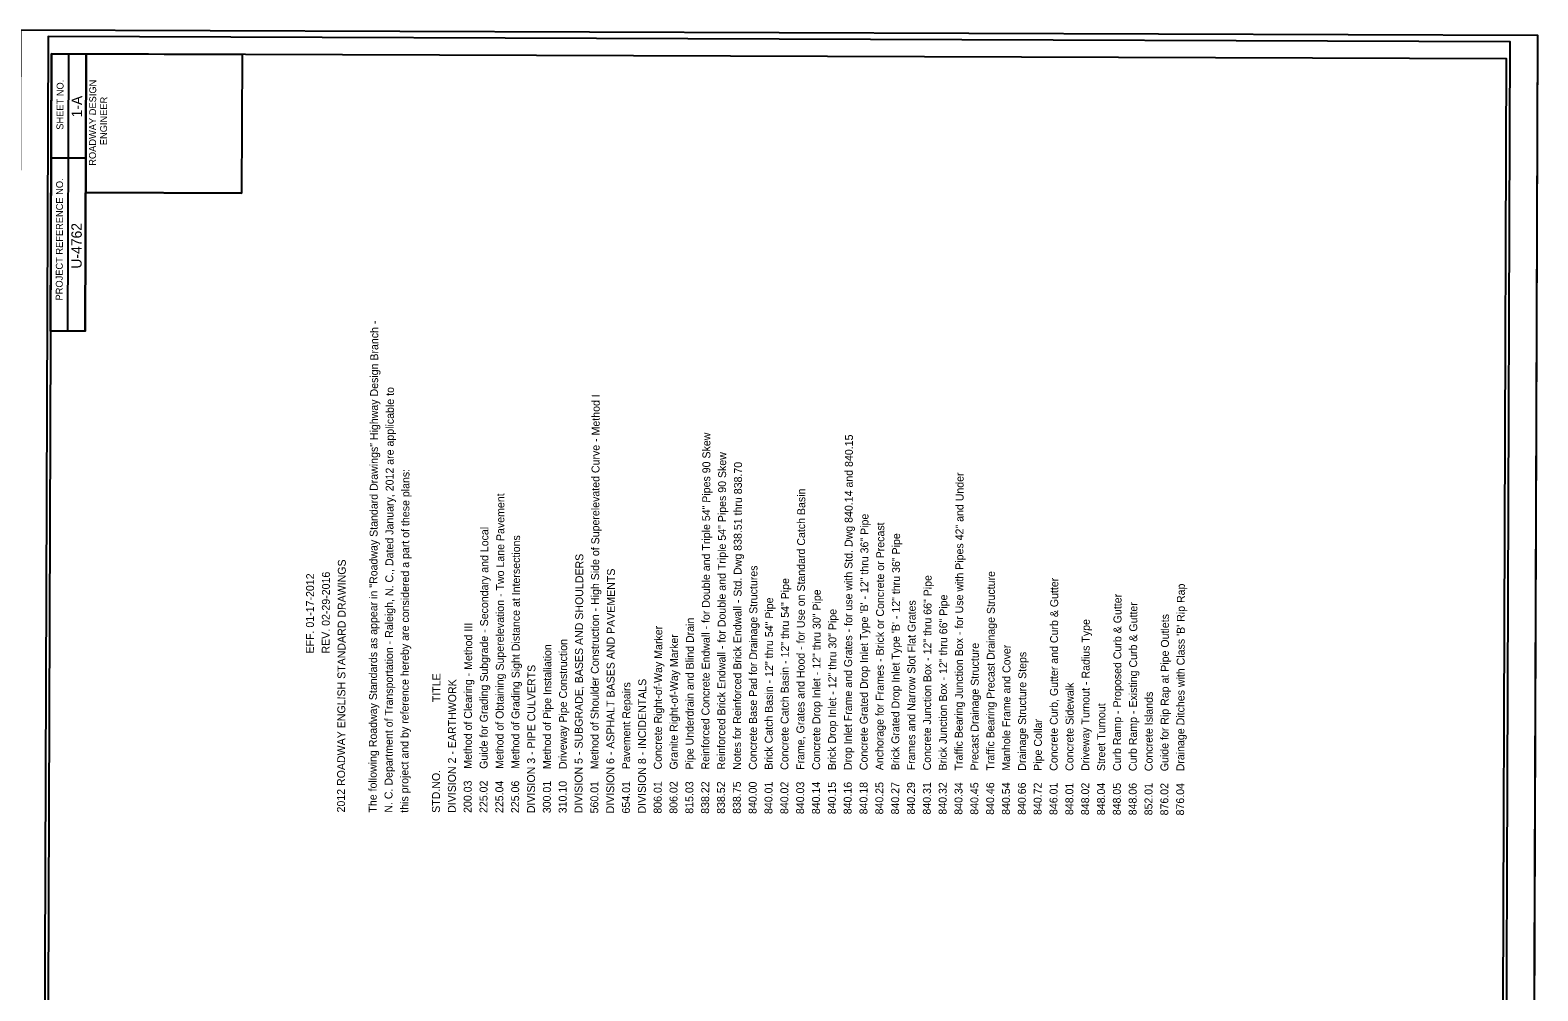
# Model space of a CAD drawing. Extents: x 2364794 to 2387902, y 795230 to 810426.
# Drawn here: x 2380284 to 2387902, y 805520 to 810372 of the extents above; entities that cross this region are included whole.
import ezdxf

# ---------------------------------------------------------------- set-up
doc = ezdxf.new("R2010")
doc.units = 0
for name, color, linetype in [('Old_Level_21', 7, 'Continuous'), ('Old_Level_22', 7, 'Continuous'), ('Old_Level_7', 7, 'Continuous'), ('Plan Sheet CELL', 7, 'Continuous'), ('Sub End Bent Cap Lines CELL', 7, 'Continuous')]:
    doc.layers.add(name, color=color, linetype=linetype)

msp = doc.modelspace()

# ---------------------------------------------------------------- linework, layer by layer
at = {"layer": 'Old_Level_21'}
msp.add_lwpolyline([(2387860.6, 798556.8), (2387902.2, 810344.7), (2380235, 810371.8), (2380193.4, 798583.9)], close=True, dxfattribs=at)
at = {"layer": 'Old_Level_22'}
msp.add_lwpolyline([(2387720.9, 798648.3), (2387762.1, 810313.7), (2380374.9, 810339.8), (2380333.7, 798674.4)], close=True, dxfattribs=at)
at = {"layer": 'Old_Level_7'}
for p, q in [((2380475.1, 808851.2), (2380480, 810251.9)), ((2380562.6, 808850.9), (2380567.5, 810251.6)), ((2380562.6, 808850.9), (2380567.5, 810251.6)), ((2380390.6, 809727.1), (2380565.7, 809726.5)), ((2380565.1, 809551.4), (2381352.4, 809548.6))]:
    msp.add_line(p, q, dxfattribs=at)
for points in [[(2380392.1, 810252.2), (2380355, 799749.2), (2387707.2, 799723.2), (2387744.3, 810226.3)], [(2380387.2, 808851.5), (2380392.1, 810252.2), (2380567.5, 810251.6), (2380562.6, 808850.9)], [(2380565.1, 809551.4), (2380567.5, 810251.6), (2381355.3, 810248.8), (2381352.8, 809548.6)]]:
    msp.add_lwpolyline(points, close=True, dxfattribs=at)
at = {"layer": 'Plan Sheet CELL'}
msp.add_line((2387860.6, 798556.8), (2387902.2, 810344.7), dxfattribs=at)

# ---------------------------------------------------------------- texts
at = {"layer": 'Old_Level_7'}
for s, height, p in [('SHEET NO.', 35.01, (2380452.4, 809869)), ('ROADWAY DESIGN', 35.011, (2380616.7, 809687.1)), ('ENGINEER', 35.01, (2380672.7, 809790.9)), ('PROJECT REFERENCE NO.', 35.011, (2380448.6, 809006.7)), ('The following Roadway Standards as appear in "Roadway Standard Drawings" Highway Design Branch -', 40, (2382034.8, 806420.2)), ('N. C. Department of Transportation - Raleigh, N. C., Dated January, 2012 are applicable to', 40, (2382114.8, 806419.9)), ('560.01    Method of Shoulder Construction - High Side of Superelevated Curve - Method I', 40, (2383154.8, 806416.2)), ('838.22    Reinforced Concrete Endwall - for Double and Triple 54" Pipes 90 Skew', 40, (2383714.8, 806414.3)), ('840.16    Drop Inlet Frame and Grates - for use with Std. Dwg 840.14 and 840.15', 40, (2384434.8, 806411.7)), ('838.52    Reinforced Brick Endwall - for Double and Triple 54" Pipes 90 Skew', 40, (2383794.8, 806414)), ('838.75    Notes for Reinforced Brick Endwall - Std. Dwg 838.51 thru 838.70', 40, (2383874.8, 806413.7)), ('this project and by reference hereby are considered a part of these plans:', 40, (2382194.8, 806419.6)), ('840.34    Traffic Bearing Junction Box - for Use with Pipes 42" and Under', 40, (2384994.8, 806409.7)), ('225.04    Method of Obtaining Superelevation - Two Lane Pavement', 40, (2382674.8, 806417.9)), ('840.03    Frame, Grates and Hood - for Use on Standard Catch Basin', 40, (2384194.8, 806412.6)), ('840.18    Concrete Grated Drop Inlet Type \'B\' - 12" thru 36" Pipe', 40, (2384514.8, 806411.4)), ('840.25    Anchorage for Frames - Brick or Concrete or Precast', 40, (2384594.8, 806411.2)), ('225.02    Guide for Grading Subgrade - Secondary and Local', 40, (2382594.8, 806418.2)), ('225.06    Method of Grading Sight Distance at Intersections', 40, (2382754.8, 806417.7)), ('840.27    Brick Grated Drop Inlet Type \'B\' - 12" thru 36" Pipe', 40, (2384674.8, 806410.9)), ('DIVISION 5 - SUBGRADE, BASES AND SHOULDERS', 40, (2383074.8, 806416.5)), ('2012 ROADWAY ENGLISH STANDARD DRAWINGS', 40, (2381874.8, 806420.8)), ('DIVISION 6 - ASPHALT BASES AND PAVEMENTS', 40, (2383234.8, 806416)), ('840.00    Concrete Base Pad for Drainage Structures', 40, (2383954.8, 806413.4)), ('                                                      EFF. 01-17-2012', 40, (2381714.8, 806421.3)), ('                                                      REV. 02-29-2016', 40, (2381794.8, 806421)), ('840.02    Concrete Catch Basin - 12" thru 54" Pipe', 40, (2384114.8, 806412.9)), ('840.31    Concrete Junction Box - 12" thru 66" Pipe', 40, (2384834.8, 806410.3)), ('840.46    Traffic Bearing Precast Drainage Structure', 40, (2385154.8, 806409.2)), ('846.01    Concrete Curb, Gutter and Curb & Gutter', 40, (2385474.8, 806408.1)), ("876.04    Drainage Ditches with Class 'B' Rip Rap", 40, (2386114.7, 806405.8)), ('840.01    Brick Catch Basin - 12" thru 54" Pipe', 40, (2384034.8, 806413.1)), ('840.14    Concrete Drop Inlet - 12" thru 30" Pipe', 40, (2384274.8, 806412.3)), ('840.32    Brick Junction Box - 12" thru 66" Pipe', 40, (2384914.8, 806410)), ('848.05    Curb Ramp - Proposed Curb & Gutter', 40, (2385794.8, 806406.9)), ('840.15    Brick Drop Inlet - 12" thru 30" Pipe', 40, (2384354.8, 806412)), ('840.29    Frames and Narrow Slot Flat Grates', 40, (2384754.8, 806410.6)), ('848.06    Curb Ramp - Existing Curb & Gutter', 40, (2385874.7, 806406.6)), ('876.02    Guide for Rip Rap at Pipe Outlets', 40, (2386034.7, 806406.1)), ('200.03    Method of Clearing - Method III', 40, (2382514.8, 806418.5)), ('806.01    Concrete Right-of-Way Marker', 40, (2383474.8, 806415.1)), ('815.03    Pipe Underdrain and Blind Drain', 40, (2383634.8, 806414.6)), ('848.02    Driveway Turnout - Radius Type', 40, (2385634.8, 806407.5)), ('300.01    Method of Pipe Installation ', 40, (2382914.8, 806417.1)), ('310.10    Driveway Pipe Construction', 40, (2382994.8, 806416.8)), ('806.02    Granite Right-of-Way Marker', 40, (2383554.8, 806414.8)), ('840.45    Precast Drainage Structure', 40, (2385074.8, 806409.5)), ('840.54    Manhole Frame and Cover', 40, (2385234.8, 806408.9)), ('840.66    Drainage Structure Steps', 40, (2385314.8, 806408.6)), ('STD.NO.                       TITLE', 40, (2382354.8, 806419.1)), ('DIVISION 3 - PIPE CULVERTS', 40, (2382834.8, 806417.4)), ('DIVISION 2 - EARTHWORK', 40, (2382434.8, 806418.8)), ('654.01    Pavement Repairs', 40, (2383314.8, 806415.7)), ('DIVISION 8 - INCIDENTALS', 40, (2383394.8, 806415.4)), ('848.01    Concrete Sidewalk', 40, (2385554.8, 806407.8)), ('848.04    Street Turnout', 40, (2385714.8, 806407.2)), ('852.01    Concrete Islands', 40, (2385954.7, 806406.4)), ('840.72    Pipe Collar', 40, (2385394.8, 806408.3))]:
    msp.add_text(s, height=height, rotation=89.79762, dxfattribs=at).set_placement(p)
at = {"layer": 'Sub End Bent Cap Lines CELL'}
for s, p in [('1-A', (2380546.8, 809930.8)), ('U-4762', (2380544.4, 809167.6))]:
    msp.add_text(s, height=52.52, rotation=89.79762, dxfattribs=at).set_placement(p)

doc.saveas('drawing.dxf')
